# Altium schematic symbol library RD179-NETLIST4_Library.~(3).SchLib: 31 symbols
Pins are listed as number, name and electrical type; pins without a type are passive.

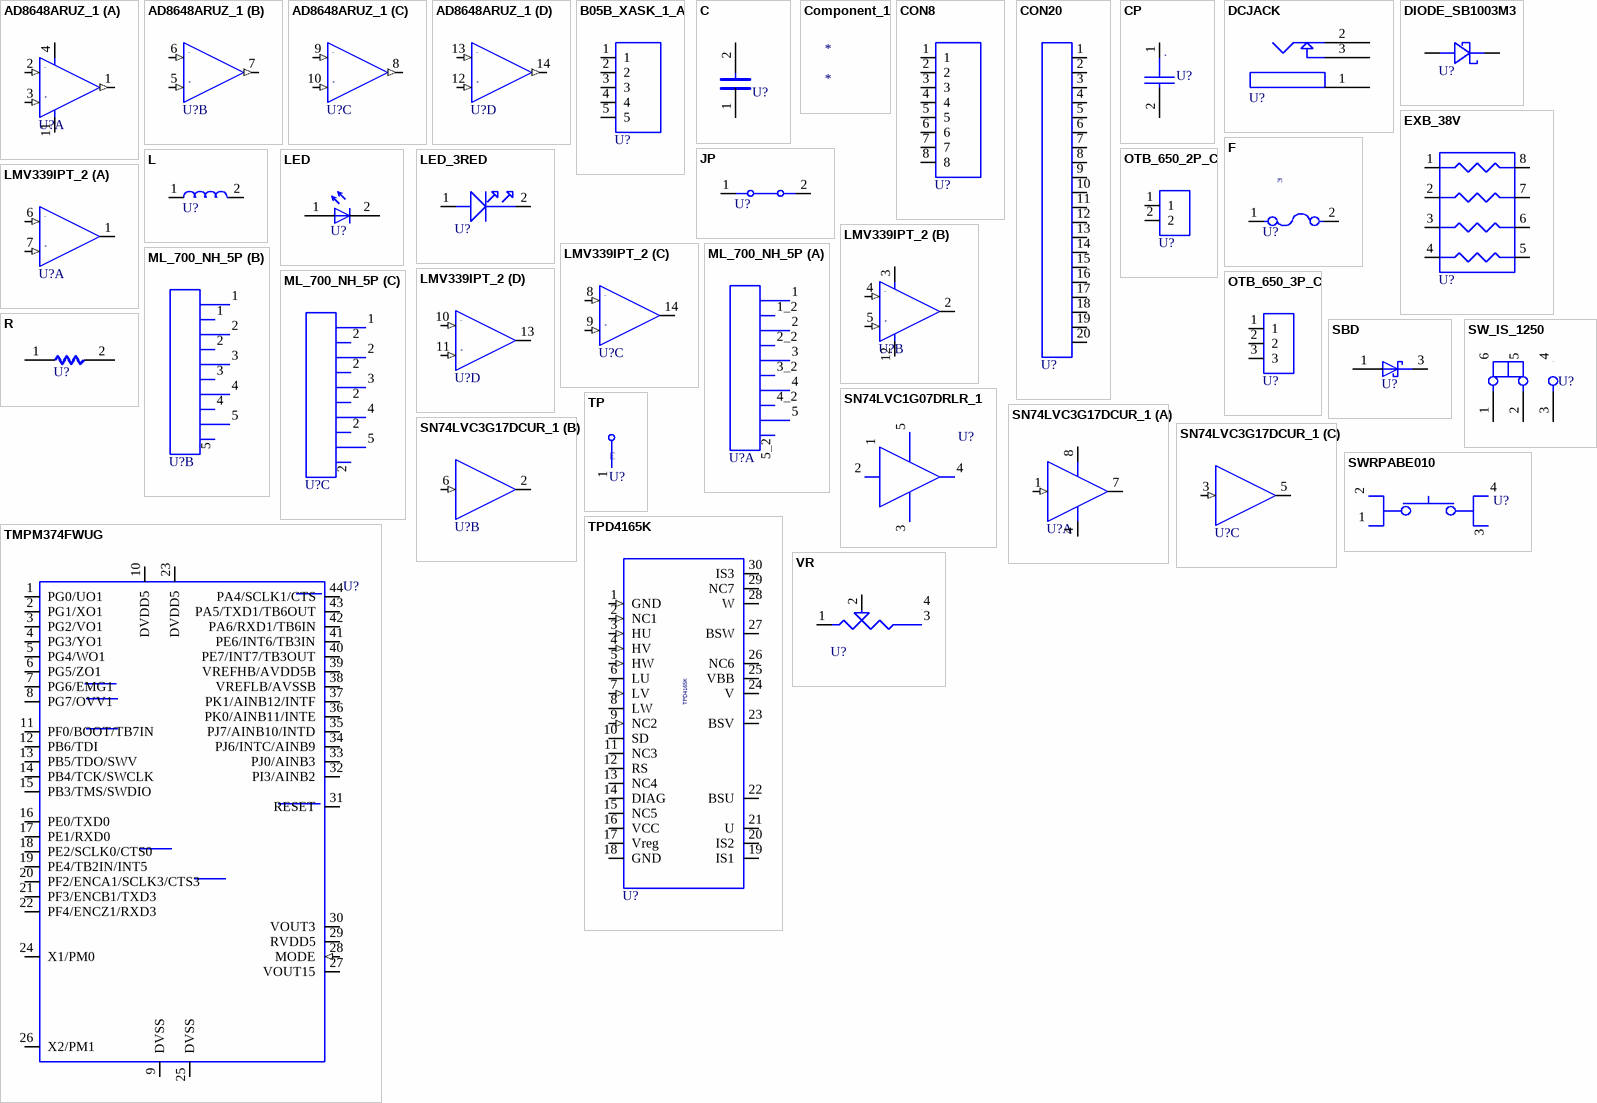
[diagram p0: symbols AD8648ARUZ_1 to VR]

## AD8648ARUZ_1
designator U?  (value not drawn)
TIME: 16:31:59; UPDATEUSER: t5459927; UPDATETIME: 15:23:55; SAVECOUNT: 10; OriginalSymbolOrigin: (0,0); SAVEAREA0: -20143,-23389,30103,13502; Altium-Right: 40
part A pins: 1 OUT (out), 2 IN- (in), 3 IN+ (in), 4 VCC, 11 GND
part B pins: 5 (in), 6 (in), 7 (out)
part C pins: 8 (out), 9 (in), 10 (in)
part D pins: 12 (in), 13 (in), 14 (out)

## B05B_XASK_1_A
designator U?  (value not drawn)
COMP: B05B-XASK-1-A; TIME: 16:31:59; UPDATEUSER: t5459927; UPDATETIME: 17:00:19; SAVECOUNT: 2; SAVEAREA0: -8887,-15544,13478,852; OriginalSymbolOrigin: (0,0); Altium-Right: 30; Altium-Bottom: 60
pins: 1, 2, 3, 4, 5

## C
designator U?  (value not drawn)
OriginalSymbolOrigin: (2540,7620); Altium-Right: 20; Altium-Bottom: 10
pins: 1, 2

## Component_1
designator *

## CON8
designator U?  (value not drawn)
ORDER: 0; TIME: 16:31:59; UPDATEUSER: t5459927; UPDATETIME: 16:59:18; SAVECOUNT: 2; SAVEAREA0: -14610,-23317,18939,1279; OriginalSymbolOrigin: (0,0); Altium-Right: 30; Altium-Bottom: 90
pins: 1, 2, 3, 4, 5, 6, 7, 8

## CON20
designator U?  (value not drawn)
TIME: 16:32:01; UPDATEUSER: t5459927; UPDATETIME: 16:59:02; SAVECOUNT: 2; SAVEAREA0: -36272,-54408,42011,2984; OriginalSymbolOrigin: (0,0); Altium-Right: 20; Altium-Bottom: 210
pins: 1, 2, 3, 4, 5, 6, 7, 8, 9, 10, 11, 12, 13, 14, 15, 16, 17, 18, 19, 20

## CP
designator U?  (value not drawn)
SAVEAREA0: -1450,-153,20294,13055; SAVECOUNT: 52; TIME: 15:02:55; UPDATEUSER: fukuda-y; UPDATETIME: 16:13:42; OriginalSymbolOrigin: (2540,10160); Altium-Right: 20
pins: 1 2, 2 1

## DCJACK
designator U?  (value not drawn)
ORDER: 0; TIME: 16:32:01; UPDATEUSER: t5459927; UPDATETIME: 16:57:29; SAVECOUNT: 2; SAVEAREA0: -1163,-13964,20286,1761; OriginalSymbolOrigin: (0,0); Altium-Right: 50
pins: 1 +5V, 2 GND, 3 NC

## DIODE_SB1003M3
designator U?  (value not drawn)
TIME: 16:32:00; UPDATEUSER: t5459927; SAVECOUNT: 1; OriginalSymbolOrigin: (0,0); Altium-Right: 30; Altium-Bottom: 20
pins: 1 ANODE, 3 CATHODE

## EXB_38V
designator U?  (value not drawn)
COMP: EXB-38V; TIME: 16:32:00; UPDATEUSER: t5459927; UPDATETIME: 16:57:52; SAVECOUNT: 2; SAVEAREA0: -8920,-20726,20901,1136; OriginalSymbolOrigin: (0,0); Altium-Right: 50; Altium-Bottom: 80
pins: 1, 2, 3, 4, 5, 6, 7, 8

## F
designator U?  (value not drawn)
OriginalSymbolOrigin: (2540,5080); Altium-Right: 40; Altium-Bottom: 20
pins: 1, 2

## JP
designator U?  (value not drawn)
OriginalSymbolOrigin: (2540,5080); Altium-Right: 40; Altium-Bottom: 20
pins: 1, 2

## L
designator U?  (value not drawn)
OriginalSymbolOrigin: (2540,5080); Altium-Right: 30; Altium-Bottom: 20
pins: 1, 2

## LED
designator U?  (value not drawn)
SAVEAREA0: -6799,-183,19247,15664; TIME: 14:49:55; UPDATEUSER: fukuda-y; UPDATETIME: 13:54:07; SAVECOUNT: 4; OriginalSymbolOrigin: (5080,7620); Altium-Right: 10; Altium-Bottom: 30
pins: 1 A, 2 C

## LED_3RED
designator U?  (value not drawn)
TIME: 16:32:00; UPDATEUSER: t5459927; SAVECOUNT: 1; OriginalSymbolOrigin: (0,0); Altium-Right: 40; Altium-Bottom: 20
pins: 1 Anode, 2 Cathode

## LMV339IPT_2
designator U?  (value not drawn)
TIME: 16:31:59; UPDATEUSER: t5459927; UPDATETIME: 15:18:09; SAVECOUNT: 11; SAVEAREA0: -12314,3023,22191,18929; OriginalSymbolOrigin: (0,0); Altium-Right: 40
part A pins: 1, 6 (in), 7 (in)
part B pins: 2 OUT, 3 VCC, 4 IN- (in), 5 IN+ (in), 12 GND
part C pins: 8 (in), 9 (in), 14
part D pins: 10 (in), 11 (in), 13

## ML_700_NH_5P
designator U?  (value not drawn)
COMP: ML-700-NH-5P; TIME: 16:32:00; UPDATEUSER: t5459927; UPDATETIME: 14:23:35; SAVECOUNT: 6; SAVEAREA0: -56271,-34402,27424,4178; OriginalSymbolOrigin: (0,0); Altium-Right: 40; Altium-Bottom: 110
part A pins: 1, 1_2 1-2, 2, 2_2 2-2, 3, 3_2 3-2, 4, 4_2 4-2, 5, 5_2 5-2
part B pins: 1, 1 1-2, 2 2-2, 2, 3 3-2, 3, 4 4-2, 4, 5 5-2, 5
part C pins: 1, 2 1-2, 2 2-2, 2, 2 3-2, 2 4-2, 2 5-2, 3, 4, 5

## OTB_650_2P_C
designator U?  (value not drawn)
COMP: OTB-650-2P-C; TIME: 16:32:00; UPDATEUSER: t5459927; UPDATETIME: 16:59:40; SAVECOUNT: 2; SAVEAREA0: -4443,-7788,6738,409; OriginalSymbolOrigin: (0,0); Altium-Right: 20; Altium-Bottom: 30
pins: 1, 2

## OTB_650_3P_C
designator U?  (value not drawn)
COMP: OTB-650-3P-C; TIME: 16:31:59; UPDATEUSER: t5459927; UPDATETIME: 16:59:57; SAVECOUNT: 2; SAVEAREA0: -6361,-10384,8548,546; OriginalSymbolOrigin: (0,0); Altium-Right: 20; Altium-Bottom: 40
pins: 1, 2, 3

## R
designator U?  (value not drawn)
OriginalSymbolOrigin: (5080,5080); Altium-Right: 20
pins: 1, 2

## SBD
designator U?  (value not drawn)
SAVEAREA0: -4630,-153,17114,13055; TIME: 14:49:55; UPDATEUSER: fukuda-y; UPDATETIME: 08:16:22; SAVECOUNT: 9; OriginalSymbolOrigin: (5080,5080); Altium-Right: 20
pins: 1 A, 3 C

## SN74LVC1G07DRLR_1
designator U?  (value not drawn)
COMP: SN74LVC1G07DRLR_0; ORDER: 0; TIME: 16:32:01; UPDATEUSER: t5459927; UPDATETIME: 09:28:13; SAVECOUNT: 2; SAVEAREA0: -35105,-23290,44922,13600; OriginalSymbolOrigin: (-2540,2540); Altium-Right: 60
pins: 1 (io), 2 INA (in), 3 GND, 4 OUTY, 5 VCC

## SN74LVC3G17DCUR_1
designator U?  (value not drawn)
COMP: SN74LVC3G17DCUR_3; ORDER: 0; TIME: 16:32:01; UPDATEUSER: t5459927; UPDATETIME: 15:47:45; SAVECOUNT: 5; SAVEAREA0: -11904,-17167,21643,7427; OriginalSymbolOrigin: (0,0); Altium-Right: 40
part A pins: 1 INA (in), 4 GND, 7 OUTY, 8 +3.3
part B pins: 2, 6 (in)
part C pins: 3 (in), 5

## SW_IS_1250
designator U?  (value not drawn)
COMP: SW_IS-1250; TIME: 16:32:00; UPDATEUSER: t5459927; UPDATETIME: 08:47:03; SAVECOUNT: 3; SAVEAREA0: -34974,-23415,45046,13471; OriginalSymbolOrigin: (-2540,0); Altium-Right: 60; Altium-Bottom: 20
pins: 1, 2, 3, 4, 5, 6

## SWRPABE010
designator U?  (value not drawn)
CDBNAME: S3; MONOCODE: E00000387; DEVICENAME: SKRELEE010; SAVECOUNT: 12; SAVEAREA0: -20086,-19151,40623,8833; TIME: 17:27:08; UPDATEUSER: t5459927; UPDATETIME: 11:11:13; OriginalSymbolOrigin: (-2540,-2540); Altium-Right: 100; Altium-Bottom: 20
pins: 1 (io), 2 (io), 3 (io), 4 (io)

## TMPM374FWUG
designator U?  (value not drawn)
TIME: 16:32:00; UPDATEUSER: t5459927; UPDATETIME: 15:11:09; SAVECOUNT: 3; SAVEAREA0: -44310,-81679,90078,-7285; OriginalSymbolOrigin: (0,0); Altium-Right: 190; Altium-Bottom: 320
pins: 1 PG0/UO1, 2 PG1/XO1, 3 PG2/VO1, 4 PG3/YO1, 5 PG4/WO1, 6 PG5/ZO1, 7 PG6/EMG1, 8 PG7/OVV1, 9 DVSS, 10 DVDD5, 11 PF0/BOOT/TB7IN, 12 PB6/TDI, 13 PB5/TDO/SWV, 14 PB4/TCK/SWCLK, 15 PB3/TMS/SWDIO, 16 PE0/TXD0, 17 PE1/RXD0, 18 PE2/SCLK0/CTS0, 19 PE4/TB2IN/INT5, 20 PF2/ENCA1/SCLK3/CTS3, 21 PF3/ENCB1/TXD3, 22 PF4/ENCZ1/RXD3, 23 DVDD5, 24 X1/PM0, 25 DVSS, 26 X2/PM1, 27 VOUT15, 28 MODE (in), 29 RVDD5, 30 VOUT3, 31 RESET, 32 PI3/AINB2, 33 PJ0/AINB3, 34 PJ6/INTC/AINB9, 35 PJ7/AINB10/INTD, 36 PK0/AINB11/INTE, 37 PK1/AINB12/INTF, 38 VREFLB/AVSSB, 39 VREFHB/AVDD5B, 40 PE7/INT7/TB3OUT, 41 PE6/INT6/TB3IN, 42 PA6/RXD1/TB6IN, 43 PA5/TXD1/TB6OUT, 44 PA4/SCLK1/CTS

## TP
designator U?  (value not drawn)
TIME: 16:12:21; UPDATEUSER: fukuda-y; UPDATETIME: 16:18:11; SAVECOUNT: 2; SAVEAREA0: -242,-92,12810,7836; OriginalSymbolOrigin: (0,7620); Altium-Right: 20; Altium-Bottom: 30
pins: 1

## TPD4165K
designator U?  (value not drawn)
COMP: TPD4164K; TIME: 16:32:01; UPDATEUSER: sptcae13; UPDATETIME: 08:46:13; SAVECOUNT: 11; SAVEAREA0: -51060,-55880,71575,0; OriginalSymbolOrigin: (0,0); Altium-Right: 80; Altium-Bottom: 220
pins: 1 GND (in), 2 NC1 (in), 3 HU (in), 4 HV (in), 5 HW (in), 6 LU, 7 LV (in), 8 LW, 9 NC2 (in), 10 SD, 11 NC3, 12 RS, 13 NC4, 14 DIAG, 15 NC5, 16 VCC, 17 Vreg, 18 GND, 19 IS1, 20 IS2, 21 U, 22 BSU, 23 BSV, 24 V, 25 VBB, 26 NC6, 27 BSW, 28 W, 29 NC7, 30 IS3

## VR
designator U?  (value not drawn)
TIME: 16:32:00; UPDATEUSER: t5459927; UPDATETIME: 09:39:06; SAVECOUNT: 2; SAVEAREA0: -14973,-11876,27253,11499; OriginalSymbolOrigin: (0,0); Altium-Right: 60; Altium-Bottom: 20
pins: 1 A, 2 WIPER, 3 B, 4 (io)

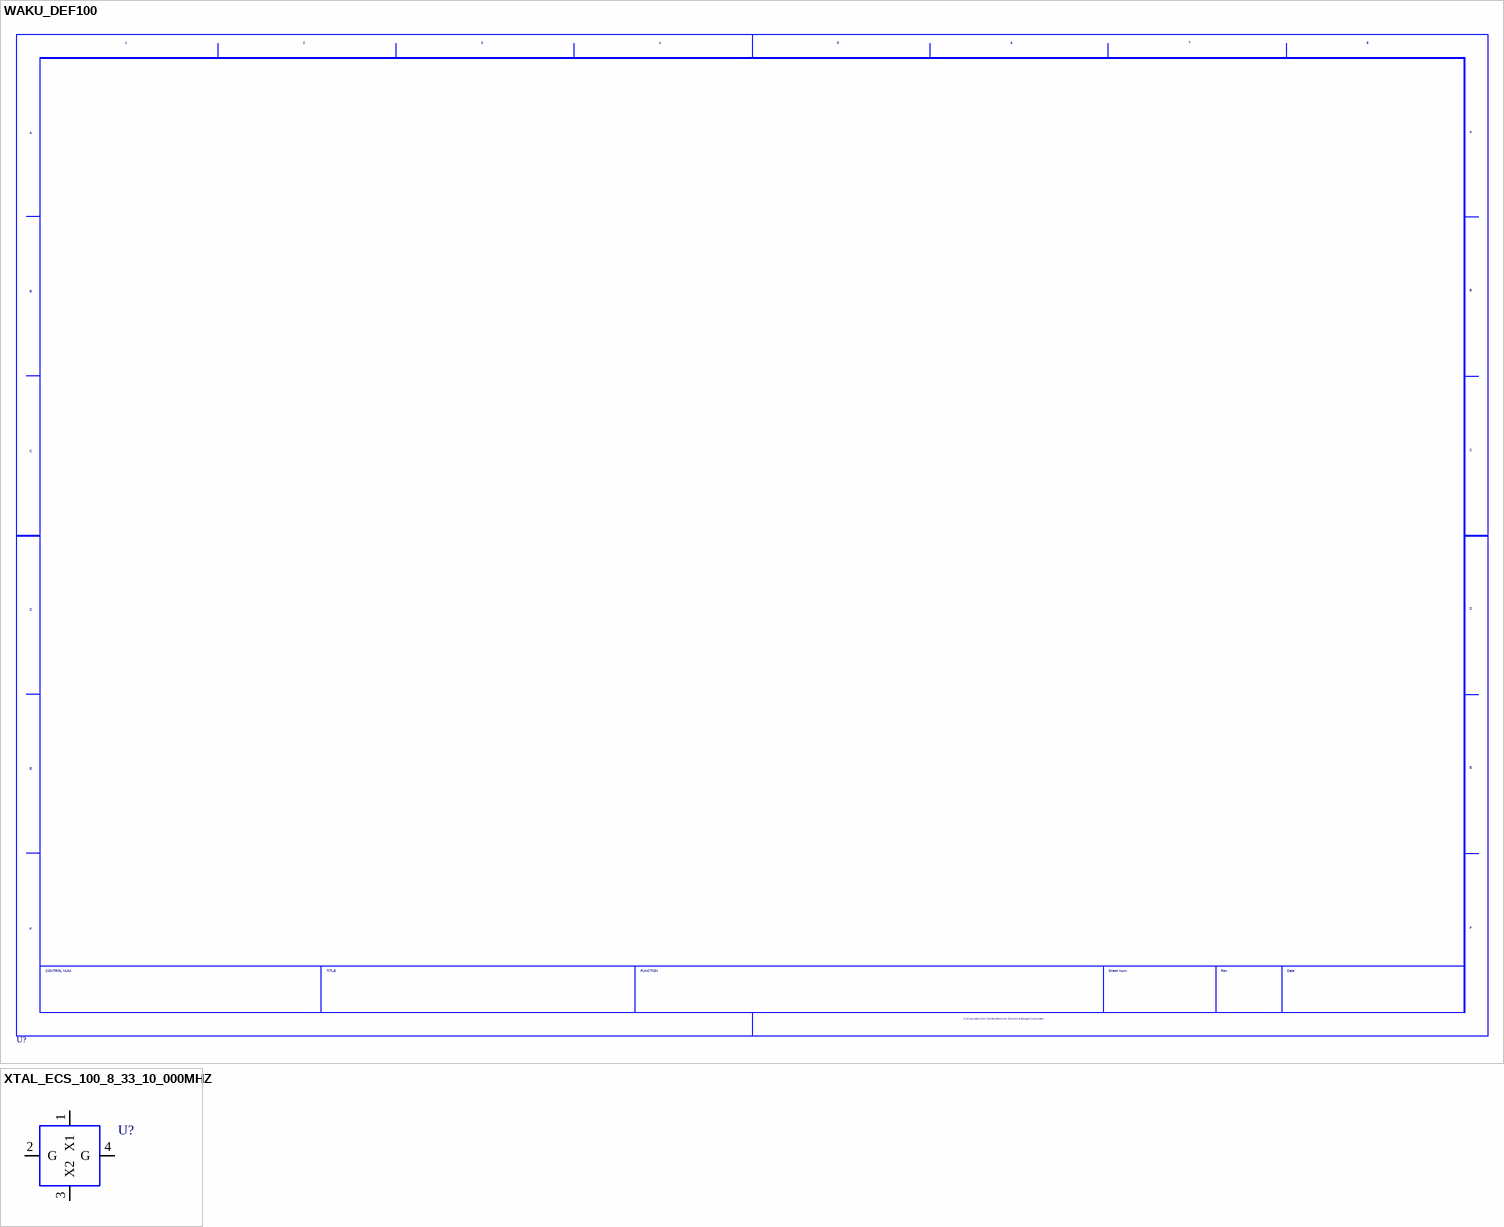
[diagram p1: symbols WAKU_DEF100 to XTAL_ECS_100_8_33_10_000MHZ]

## WAKU_DEF100
designator U?  (value not drawn)
PLOTTIME: HH:MM; SAVEAREA0: 129921,-74212,504566,96496; TIME: 14:30:25; UPDATEUSER: sptcae13; UPDATETIME: 08:43:21; SAVECOUNT: 10; OriginalSymbolOrigin: (10160,284480); Altium-Right: 1570; Altium-Bottom: 1070

## XTAL_ECS_100_8_33_10_000MHZ
designator U?  (value not drawn)
COMP: Xtal_ECS-100-8-33-10.000MHZ; ORDER: 1; TIME: 16:32:00; UPDATEUSER: t5459927; UPDATETIME: 15:12:21; SAVECOUNT: 3; SAVEAREA0: -55012,-32573,65020,22757; OriginalSymbolOrigin: (0,0); Altium-Right: 40
pins: 1 X1, 2 G, 3 X2, 4 G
